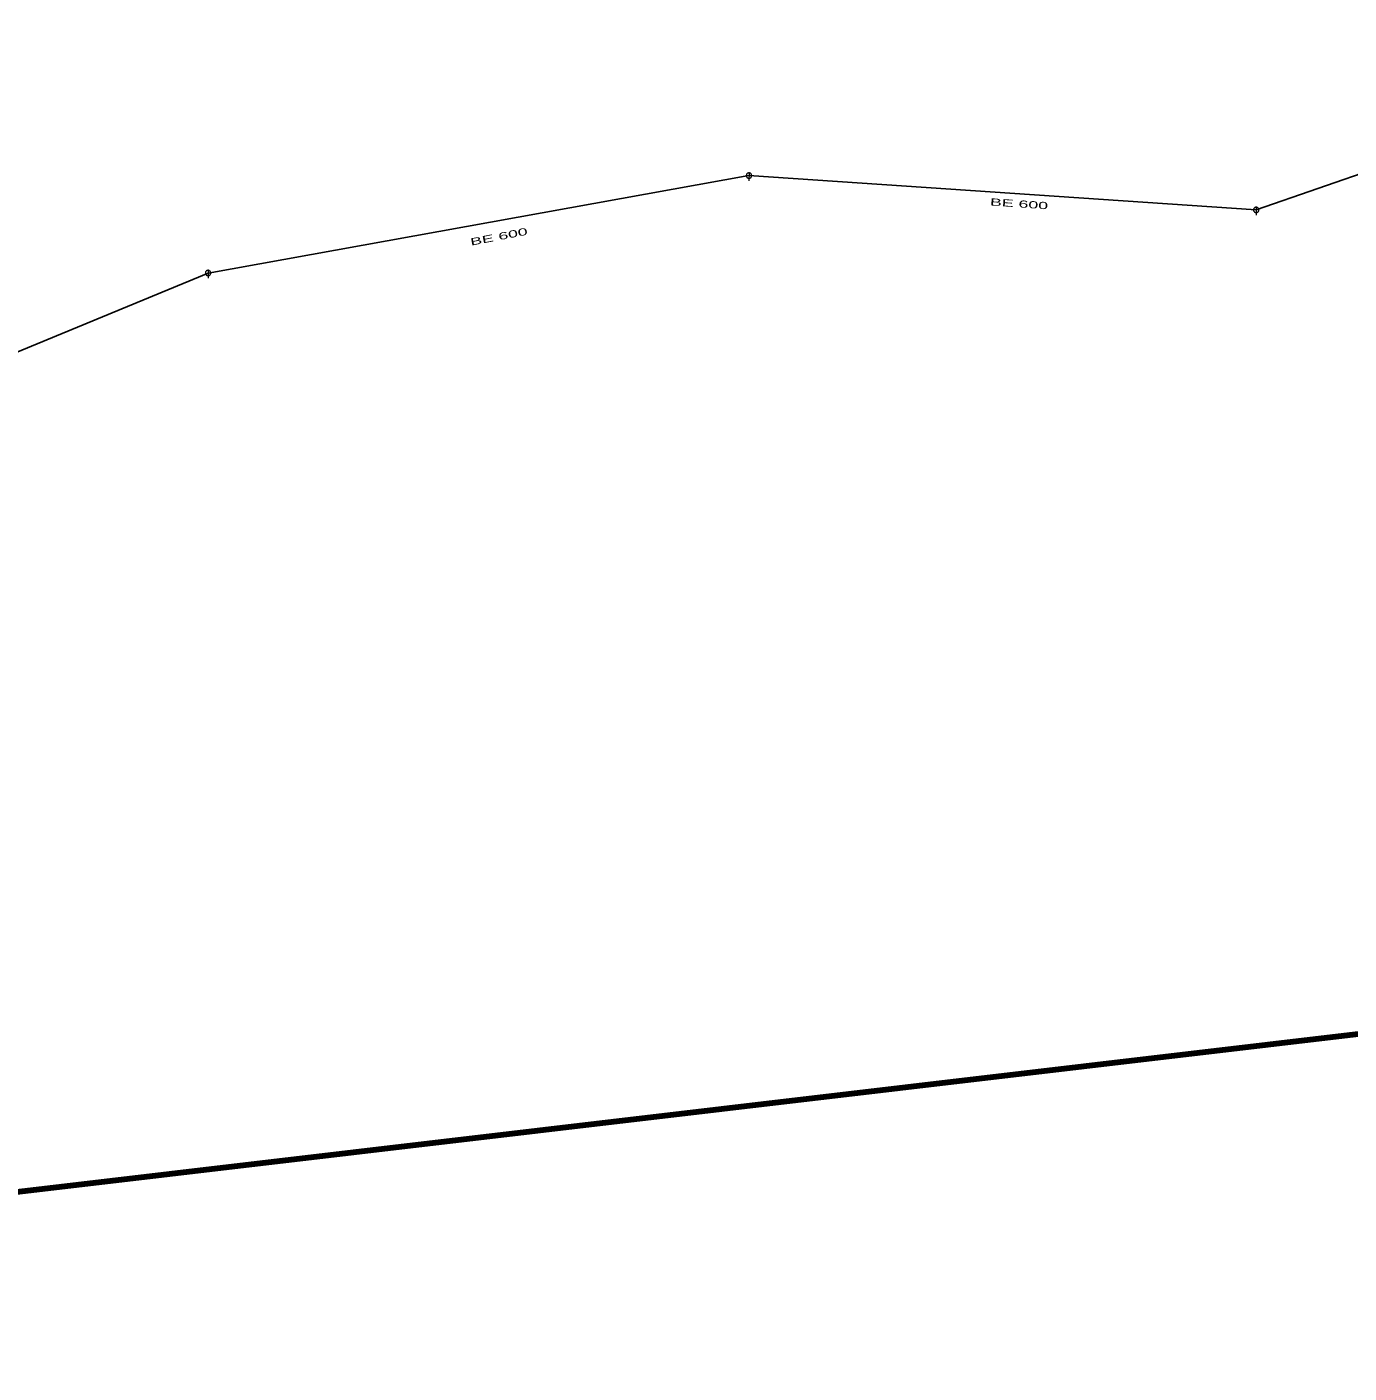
# Model space of a CAD drawing. Extents: x -687468 to -685917, y -974192 to -973456.
# Drawn here: x -686537.4 to -686414.5, y -974012.2 to -973887 of the extents above; entities that cross this region are included whole.
import ezdxf
from ezdxf.enums import TextEntityAlignment as Align

# ---------------------------------------------------------------- set-up
doc = ezdxf.new("R2010")
doc.units = 0
doc.header["$LTSCALE"] = 0.27
for name, color, linetype, lineweight in [('1', 7, 'Continuous', 13), ('14', 7, 'Continuous', 25), ('22', 7, 'Continuous', 13), ('27', 7, 'Continuous', 158)]:
    doc.layers.add(name, color=color, linetype=linetype, lineweight=lineweight)

msp = doc.modelspace()

# ---------------------------------------------------------------- linework, layer by layer
at = {"layer": '14'}
for p, q in [((-686374.016, -973887.013), (-686423.106, -973904.035)), ((-686470.274, -973900.841), (-686520.577, -973909.902)), ((-686423.106, -973904.035), (-686470.274, -973900.841)), ((-686520.577, -973909.902), (-686564.996, -973928.285)), ((-686200.654, -973955.608), (-686609.228, -974003.734))]:
    msp.add_line(p, q, dxfattribs=at)
at = {"layer": '22'}
for p, q in [((-686470.273, -973900.589), (-686470.274, -973901.333)), ((-686423.105, -973903.783), (-686423.106, -973904.527)), ((-686520.576, -973909.65), (-686520.577, -973910.394))]:
    msp.add_line(p, q, dxfattribs=at)
for points in [[(-686470.022, -973900.841), (-686470.023, -973900.815), (-686470.027, -973900.789), (-686470.033, -973900.763), (-686470.043, -973900.739), (-686470.055, -973900.715), (-686470.069, -973900.693), (-686470.086, -973900.672), (-686470.104, -973900.654), (-686470.125, -973900.637), (-686470.147, -973900.623), (-686470.171, -973900.611), (-686470.195, -973900.601), (-686470.221, -973900.595), (-686470.247, -973900.591), (-686470.273, -973900.589), (-686470.299, -973900.59), (-686470.325, -973900.594), (-686470.351, -973900.6), (-686470.376, -973900.61), (-686470.399, -973900.622), (-686470.421, -973900.636), (-686470.442, -973900.653), (-686470.46, -973900.671), (-686470.477, -973900.692), (-686470.491, -973900.714), (-686470.503, -973900.738), (-686470.513, -973900.762), (-686470.52, -973900.788), (-686470.524, -973900.814), (-686470.526, -973900.84), (-686470.525, -973900.866), (-686470.521, -973900.892), (-686470.514, -973900.918), (-686470.504, -973900.943), (-686470.492, -973900.966), (-686470.478, -973900.988), (-686470.461, -973901.009), (-686470.443, -973901.027), (-686470.422, -973901.044), (-686470.4, -973901.058), (-686470.377, -973901.07), (-686470.352, -973901.08), (-686470.326, -973901.087), (-686470.3, -973901.091), (-686470.274, -973901.093), (-686470.248, -973901.092), (-686470.222, -973901.088), (-686470.196, -973901.081), (-686470.172, -973901.071), (-686470.148, -973901.059), (-686470.126, -973901.045), (-686470.105, -973901.028), (-686470.087, -973901.01), (-686470.07, -973900.989), (-686470.056, -973900.967), (-686470.044, -973900.944), (-686470.034, -973900.919), (-686470.028, -973900.893), (-686470.024, -973900.867)], [(-686422.854, -973904.035), (-686422.855, -973904.009), (-686422.859, -973903.983), (-686422.865, -973903.957), (-686422.875, -973903.933), (-686422.887, -973903.909), (-686422.901, -973903.887), (-686422.918, -973903.866), (-686422.936, -973903.848), (-686422.957, -973903.831), (-686422.979, -973903.817), (-686423.003, -973903.805), (-686423.027, -973903.795), (-686423.053, -973903.789), (-686423.079, -973903.785), (-686423.105, -973903.783), (-686423.131, -973903.784), (-686423.157, -973903.788), (-686423.183, -973903.794), (-686423.208, -973903.804), (-686423.231, -973903.816), (-686423.253, -973903.83), (-686423.274, -973903.847), (-686423.292, -973903.865), (-686423.309, -973903.886), (-686423.323, -973903.908), (-686423.335, -973903.932), (-686423.345, -973903.956), (-686423.352, -973903.982), (-686423.356, -973904.008), (-686423.358, -973904.034), (-686423.357, -973904.06), (-686423.353, -973904.086), (-686423.346, -973904.112), (-686423.336, -973904.137), (-686423.324, -973904.16), (-686423.31, -973904.182), (-686423.293, -973904.203), (-686423.275, -973904.221), (-686423.254, -973904.238), (-686423.232, -973904.252), (-686423.209, -973904.264), (-686423.184, -973904.274), (-686423.158, -973904.281), (-686423.132, -973904.285), (-686423.106, -973904.287), (-686423.08, -973904.286), (-686423.054, -973904.282), (-686423.028, -973904.275), (-686423.004, -973904.265), (-686422.98, -973904.253), (-686422.958, -973904.239), (-686422.937, -973904.222), (-686422.919, -973904.204), (-686422.902, -973904.183), (-686422.888, -973904.161), (-686422.876, -973904.138), (-686422.866, -973904.113), (-686422.86, -973904.087), (-686422.856, -973904.061)], [(-686520.325, -973909.902), (-686520.326, -973909.876), (-686520.33, -973909.85), (-686520.336, -973909.824), (-686520.346, -973909.8), (-686520.358, -973909.776), (-686520.372, -973909.754), (-686520.389, -973909.733), (-686520.407, -973909.715), (-686520.428, -973909.698), (-686520.45, -973909.684), (-686520.474, -973909.672), (-686520.498, -973909.662), (-686520.524, -973909.656), (-686520.55, -973909.652), (-686520.576, -973909.65), (-686520.602, -973909.651), (-686520.628, -973909.655), (-686520.654, -973909.661), (-686520.679, -973909.671), (-686520.702, -973909.683), (-686520.724, -973909.697), (-686520.745, -973909.714), (-686520.763, -973909.732), (-686520.78, -973909.753), (-686520.794, -973909.775), (-686520.806, -973909.799), (-686520.816, -973909.823), (-686520.823, -973909.849), (-686520.827, -973909.875), (-686520.829, -973909.901), (-686520.828, -973909.927), (-686520.824, -973909.953), (-686520.817, -973909.979), (-686520.807, -973910.004), (-686520.795, -973910.027), (-686520.781, -973910.049), (-686520.764, -973910.07), (-686520.746, -973910.088), (-686520.725, -973910.105), (-686520.703, -973910.119), (-686520.68, -973910.131), (-686520.655, -973910.141), (-686520.629, -973910.148), (-686520.603, -973910.152), (-686520.577, -973910.154), (-686520.551, -973910.153), (-686520.525, -973910.149), (-686520.499, -973910.142), (-686520.475, -973910.132), (-686520.451, -973910.12), (-686520.429, -973910.106), (-686520.408, -973910.089), (-686520.39, -973910.071), (-686520.373, -973910.05), (-686520.359, -973910.028), (-686520.347, -973910.005), (-686520.337, -973909.98), (-686520.331, -973909.954), (-686520.327, -973909.928)]]:
    msp.add_lwpolyline(points, close=True, dxfattribs=at)
at = {"layer": '27'}
msp.add_lwpolyline([(-686200.654, -973955.608), (-686609.228, -974003.734), (-687014.163, -974137.428)], dxfattribs=at)
msp.add_lwpolyline([(-686200.654, -973955.608), (-686609.228, -974003.734), (-687014.163, -974137.428)], dxfattribs=at)

# ---------------------------------------------------------------- texts
at = {"layer": '1', "width": 1.85}
for rotation, p in [(356, (-686445.183, -973903.797)), (11, (-686493.467, -973906.844))]:
    msp.add_text('BE 600', height=0.6667, rotation=rotation, dxfattribs=at).set_placement(p, align=Align.CENTER)

doc.saveas('drawing.dxf')
